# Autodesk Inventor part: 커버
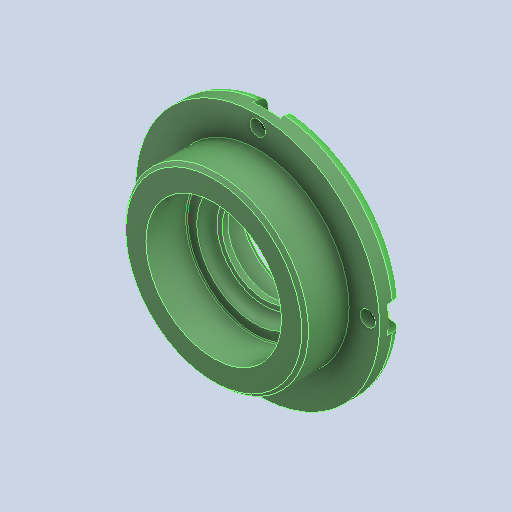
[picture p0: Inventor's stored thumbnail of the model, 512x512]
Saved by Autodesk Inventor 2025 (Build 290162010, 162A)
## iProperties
Created: 2024-07
Part Number: 커버
Material: 강철, 연강
Document SubType Name: Modeling
Designer: 계정
Density: 7.86 g/cm^3
Appearance: 기본값
Company: 한국ATC센터
Author: jhkim
Revision Number: 1
Sending System: Autodesk Inventor 2025
Preprocessor: ST-DEVELOPER v20
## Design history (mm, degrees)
feature "솔리드1"
node "솔리드2"
